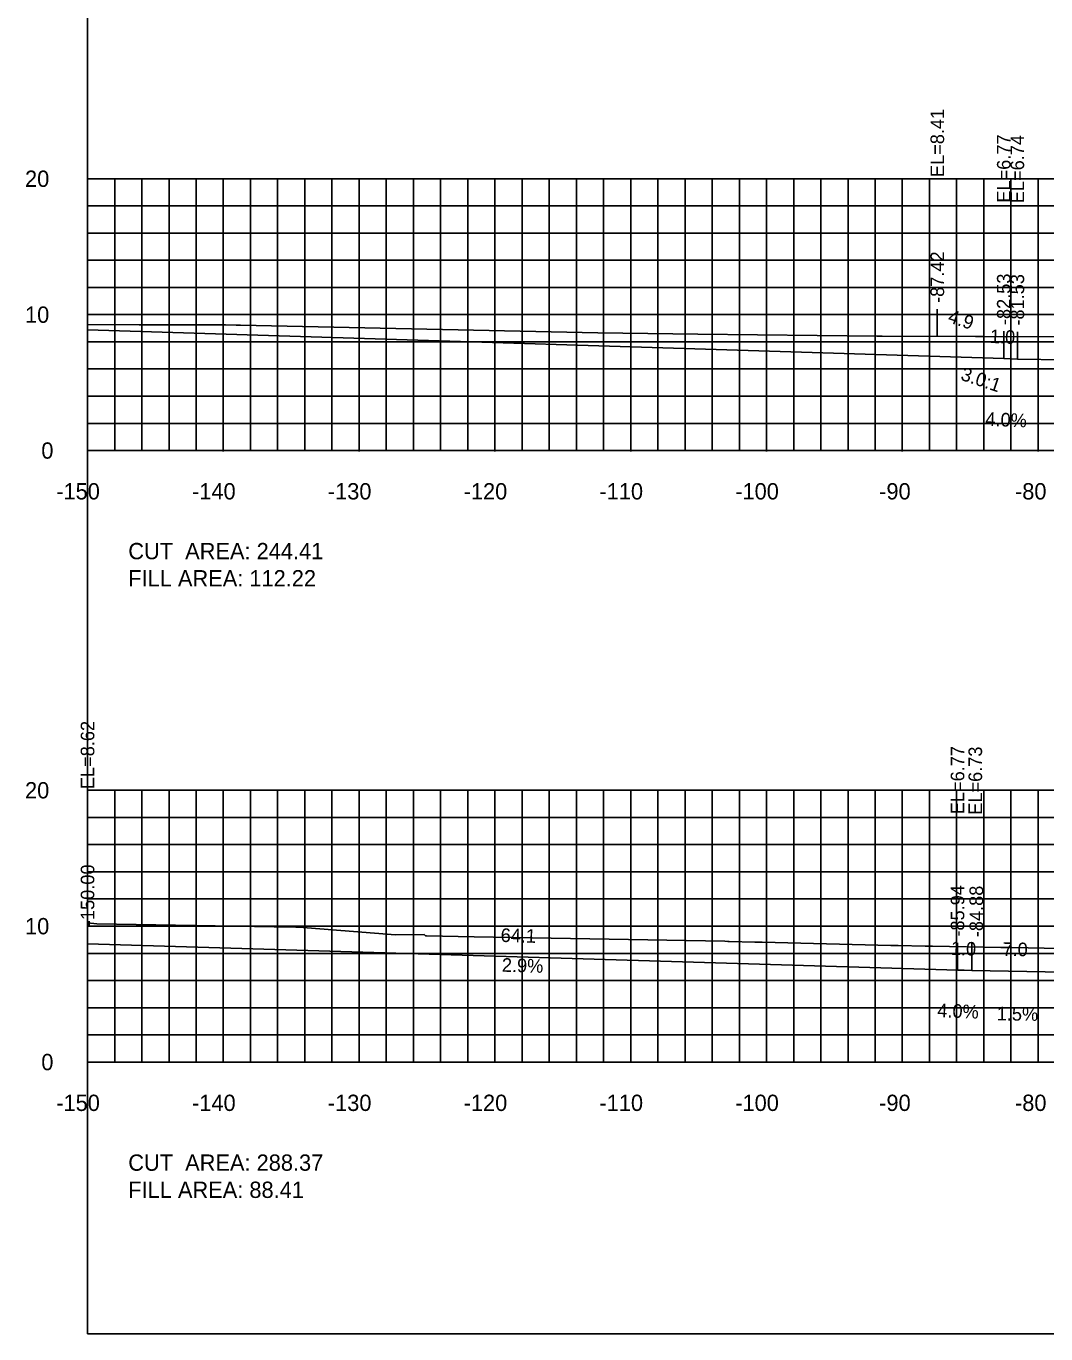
# Model space of a CAD drawing. Extents: x 1797419 to 1809236, y 248759 to 251512.
# Drawn here: x 1806216.5 to 1806291.6, y 250079.4 to 250175.7 of the extents above; entities that cross this region are included whole.
import ezdxf

# ---------------------------------------------------------------- set-up
doc = ezdxf.new("R2010")
doc.units = 0
for name, color, linetype in [('10', 7, 'Continuous'), ('3', 7, 'Continuous'), ('31', 7, 'Continuous'), ('4', 7, 'Continuous'), ('60', 7, 'Continuous'), ('ANNO-TXT', 7, 'Continuous'), ('CL-CNST', 7, 'Continuous'), ('Level 62', 7, 'Continuous'), ('M-ROADS', 7, 'Continuous')]:
    doc.layers.add(name, color=color, linetype=linetype)

msp = doc.modelspace()

# ---------------------------------------------------------------- linework, layer by layer
for p, q in [((1806283.579, 250152.837), (1806283.579, 250154.837)), ((1806288.472, 250151.207), (1806288.472, 250153.207)), ((1806289.472, 250151.167), (1806289.472, 250153.167)), ((1806221.002, 250108.05), (1806221.002, 250110.05)), ((1806285.065, 250106.206), (1806285.065, 250108.206)), ((1806286.118, 250106.164), (1806286.118, 250108.164))]:
    msp.add_line(p, q)
msp.add_lwpolyline([(1806221.002, 250079.432), (1806521.002, 250079.432), (1806521.002, 250269.432), (1806221.002, 250269.432)], close=True)
at = {"layer": '60'}
for p, q in [((1806220.942, 250164.432), (1806221.002, 250164.432)), ((1806221.002, 250144.432), (1806221.002, 250164.432)), ((1806220.942, 250154.432), (1806221.002, 250154.432)), ((1806220.942, 250144.432), (1806221.002, 250144.432)), ((1806221.002, 250144.432), (1806521.002, 250144.432)), ((1806221.002, 250144.372), (1806221.002, 250144.432)), ((1806231.002, 250144.372), (1806231.002, 250144.432)), ((1806241.002, 250144.372), (1806241.002, 250144.432)), ((1806251.002, 250144.372), (1806251.002, 250144.432)), ((1806261.002, 250144.372), (1806261.002, 250144.432)), ((1806271.002, 250144.372), (1806271.002, 250144.432)), ((1806281.002, 250144.372), (1806281.002, 250144.432)), ((1806291.002, 250144.372), (1806291.002, 250144.432)), ((1806220.942, 250119.432), (1806221.002, 250119.432)), ((1806221.002, 250099.432), (1806221.002, 250119.432)), ((1806220.942, 250109.432), (1806221.002, 250109.432)), ((1806220.942, 250099.432), (1806221.002, 250099.432)), ((1806221.002, 250099.432), (1806521.002, 250099.432)), ((1806221.002, 250099.372), (1806221.002, 250099.432)), ((1806231.002, 250099.372), (1806231.002, 250099.432)), ((1806241.002, 250099.372), (1806241.002, 250099.432)), ((1806251.002, 250099.372), (1806251.002, 250099.432)), ((1806261.002, 250099.372), (1806261.002, 250099.432)), ((1806271.002, 250099.372), (1806271.002, 250099.432)), ((1806281.002, 250099.372), (1806281.002, 250099.432)), ((1806291.002, 250099.372), (1806291.002, 250099.432))]:
    msp.add_line(p, q, dxfattribs=at)
at = {"layer": 'CL-CNST'}
for points in [[(1806221.002, 250153.306), (1806288.472, 250151.207), (1806288.958, 250151.188), (1806289.472, 250151.167), (1806292.935, 250151.115), (1806296.472, 250151.062), (1806297.35, 250151.027), (1806298.472, 250150.982), (1806298.801, 250150.982), (1806298.808, 250150.962), (1806298.969, 250150.482), (1806300.378, 250150.595), (1806300.969, 250150.642), (1806349.002, 250151.698), (1806351.001, 250151.742), (1806351.041, 250151.859), (1806351.172, 250152.242), (1806351.502, 250152.242), (1806371.001, 250153.022), (1806378.502, 250152.406)], [(1806221.002, 250108.134), (1806285.085, 250106.205), (1806285.118, 250106.204), (1806285.564, 250106.186), (1806286.118, 250106.164), (1806291.509, 250106.083), (1806293.118, 250106.059)]]:
    msp.add_lwpolyline(points, dxfattribs=at)
at = {"layer": 'Level 62'}
for p, q in [((1806221.002, 250164.432), (1806521.002, 250164.432)), ((1806221.002, 250144.432), (1806221.002, 250164.432)), ((1806223.002, 250144.432), (1806223.002, 250164.432)), ((1806225.002, 250144.432), (1806225.002, 250164.432)), ((1806227.002, 250144.432), (1806227.002, 250164.432)), ((1806229.002, 250144.432), (1806229.002, 250164.432)), ((1806231.002, 250144.432), (1806231.002, 250164.432)), ((1806233.002, 250144.432), (1806233.002, 250164.432)), ((1806235.002, 250144.432), (1806235.002, 250164.432)), ((1806237.002, 250144.432), (1806237.002, 250164.432)), ((1806239.002, 250144.432), (1806239.002, 250164.432)), ((1806241.002, 250144.432), (1806241.002, 250164.432)), ((1806243.002, 250144.432), (1806243.002, 250164.432)), ((1806245.002, 250144.432), (1806245.002, 250164.432)), ((1806247.002, 250144.432), (1806247.002, 250164.432)), ((1806249.002, 250144.432), (1806249.002, 250164.432)), ((1806251.002, 250144.432), (1806251.002, 250164.432)), ((1806253.002, 250144.432), (1806253.002, 250164.432)), ((1806255.002, 250144.432), (1806255.002, 250164.432)), ((1806257.002, 250144.432), (1806257.002, 250164.432)), ((1806259.002, 250144.432), (1806259.002, 250164.432)), ((1806261.002, 250144.432), (1806261.002, 250164.432)), ((1806263.002, 250144.432), (1806263.002, 250164.432)), ((1806265.002, 250144.432), (1806265.002, 250164.432)), ((1806267.002, 250144.432), (1806267.002, 250164.432)), ((1806269.002, 250144.432), (1806269.002, 250164.432)), ((1806271.002, 250144.432), (1806271.002, 250164.432)), ((1806273.002, 250144.432), (1806273.002, 250164.432)), ((1806275.002, 250144.432), (1806275.002, 250164.432)), ((1806277.002, 250144.432), (1806277.002, 250164.432)), ((1806279.002, 250144.432), (1806279.002, 250164.432)), ((1806281.002, 250144.432), (1806281.002, 250164.432)), ((1806283.002, 250144.432), (1806283.002, 250164.432)), ((1806285.002, 250144.432), (1806285.002, 250164.432)), ((1806287.002, 250144.432), (1806287.002, 250164.432)), ((1806289.002, 250144.432), (1806289.002, 250164.432)), ((1806291.002, 250144.432), (1806291.002, 250164.432)), ((1806221.002, 250162.432), (1806521.002, 250162.432)), ((1806221.002, 250160.432), (1806521.002, 250160.432)), ((1806221.002, 250158.432), (1806521.002, 250158.432)), ((1806221.002, 250156.432), (1806521.002, 250156.432)), ((1806221.002, 250154.432), (1806521.002, 250154.432)), ((1806221.002, 250152.432), (1806521.002, 250152.432)), ((1806221.002, 250150.432), (1806521.002, 250150.432)), ((1806221.002, 250148.432), (1806521.002, 250148.432)), ((1806221.002, 250146.432), (1806521.002, 250146.432)), ((1806221.002, 250144.432), (1806521.002, 250144.432)), ((1806221.002, 250119.432), (1806521.002, 250119.432)), ((1806221.002, 250099.432), (1806221.002, 250119.432)), ((1806223.002, 250099.432), (1806223.002, 250119.432)), ((1806225.002, 250099.432), (1806225.002, 250119.432)), ((1806227.002, 250099.432), (1806227.002, 250119.432)), ((1806229.002, 250099.432), (1806229.002, 250119.432)), ((1806231.002, 250099.432), (1806231.002, 250119.432)), ((1806233.002, 250099.432), (1806233.002, 250119.432)), ((1806235.002, 250099.432), (1806235.002, 250119.432)), ((1806237.002, 250099.432), (1806237.002, 250119.432)), ((1806239.002, 250099.432), (1806239.002, 250119.432)), ((1806241.002, 250099.432), (1806241.002, 250119.432)), ((1806243.002, 250099.432), (1806243.002, 250119.432)), ((1806245.002, 250099.432), (1806245.002, 250119.432)), ((1806247.002, 250099.432), (1806247.002, 250119.432)), ((1806249.002, 250099.432), (1806249.002, 250119.432)), ((1806251.002, 250099.432), (1806251.002, 250119.432)), ((1806253.002, 250099.432), (1806253.002, 250119.432)), ((1806255.002, 250099.432), (1806255.002, 250119.432)), ((1806257.002, 250099.432), (1806257.002, 250119.432)), ((1806259.002, 250099.432), (1806259.002, 250119.432)), ((1806261.002, 250099.432), (1806261.002, 250119.432)), ((1806263.002, 250099.432), (1806263.002, 250119.432)), ((1806265.002, 250099.432), (1806265.002, 250119.432)), ((1806267.002, 250099.432), (1806267.002, 250119.432)), ((1806269.002, 250099.432), (1806269.002, 250119.432)), ((1806271.002, 250099.432), (1806271.002, 250119.432)), ((1806273.002, 250099.432), (1806273.002, 250119.432)), ((1806275.002, 250099.432), (1806275.002, 250119.432)), ((1806277.002, 250099.432), (1806277.002, 250119.432)), ((1806279.002, 250099.432), (1806279.002, 250119.432)), ((1806281.002, 250099.432), (1806281.002, 250119.432)), ((1806283.002, 250099.432), (1806283.002, 250119.432)), ((1806285.002, 250099.432), (1806285.002, 250119.432)), ((1806287.002, 250099.432), (1806287.002, 250119.432)), ((1806289.002, 250099.432), (1806289.002, 250119.432)), ((1806291.002, 250099.432), (1806291.002, 250119.432)), ((1806221.002, 250117.432), (1806521.002, 250117.432)), ((1806221.002, 250115.432), (1806521.002, 250115.432)), ((1806221.002, 250113.432), (1806521.002, 250113.432)), ((1806221.002, 250111.432), (1806521.002, 250111.432)), ((1806221.002, 250109.432), (1806521.002, 250109.432)), ((1806221.002, 250107.432), (1806521.002, 250107.432)), ((1806221.002, 250105.432), (1806521.002, 250105.432)), ((1806221.002, 250103.432), (1806521.002, 250103.432)), ((1806221.002, 250101.432), (1806521.002, 250101.432)), ((1806221.002, 250099.432), (1806521.002, 250099.432))]:
    msp.add_line(p, q, dxfattribs=at)
at = {"layer": 'M-ROADS'}
for points in [[(1806221.002, 250153.705), (1806224.794, 250153.692), (1806230.688, 250153.671), (1806231.168, 250153.673), (1806231.936, 250153.659), (1806231.976, 250153.66), (1806232.276, 250153.648), (1806258.57, 250153.093), (1806265.934, 250152.985), (1806279.121, 250152.852), (1806279.308, 250152.853), (1806279.527, 250152.851), (1806286.384, 250152.828), (1806286.571, 250152.828), (1806286.919, 250152.828), (1806298.866, 250152.773)], [(1806221.002, 250109.673), (1806221.689, 250109.615), (1806234.756, 250109.39), (1806236.338, 250109.348), (1806236.561, 250109.356), (1806243.677, 250108.805), (1806245.787, 250108.827), (1806245.894, 250108.727), (1806245.9, 250108.726), (1806245.926, 250108.72), (1806245.95, 250108.714), (1806245.962, 250108.711), (1806249.464, 250108.648), (1806267.943, 250108.32), (1806268.141, 250108.315), (1806268.246, 250108.305), (1806270.139, 250108.245), (1806270.294, 250108.245), (1806270.676, 250108.244), (1806280.166, 250108.014), (1806280.63, 250108.005), (1806280.708, 250108.003), (1806282.694, 250107.966), (1806283.235, 250107.966), (1806288.261, 250107.87), (1806289.077, 250107.854), (1806295.03, 250107.749)]]:
    msp.add_lwpolyline(points, dxfattribs=at)

# ---------------------------------------------------------------- texts
msp.add_text('3.0:1', height=1, rotation=341.57445).set_placement((1806285.235, 250149.65))
at = {"layer": '10'}
for s, p in [('-150', (1806218.698, 250140.832)), ('-140', (1806228.698, 250140.832)), ('-130', (1806238.698, 250140.832)), ('-120', (1806248.698, 250140.832)), ('-110', (1806258.698, 250140.832)), ('-100', (1806268.698, 250140.832)), ('-90', (1806279.298, 250140.832)), ('-80', (1806289.298, 250140.832)), ('-150', (1806218.698, 250095.832)), ('-140', (1806228.698, 250095.832)), ('-130', (1806238.698, 250095.832)), ('-120', (1806248.698, 250095.832)), ('-110', (1806258.698, 250095.832)), ('-100', (1806268.698, 250095.832)), ('-90', (1806279.298, 250095.832)), ('-80', (1806289.298, 250095.832))]:
    msp.add_text(s, height=1.2, dxfattribs=at).set_placement(p)
at = {"layer": '3'}
for s, p in [('EL=8.41', (1806284.079, 250164.554)), ('EL=6.77', (1806288.972, 250162.672)), ('EL=6.74', (1806289.972, 250162.632)), ('-87.42', (1806284.079, 250155.294)), ('-82.53', (1806288.972, 250153.664)), ('-81.53', (1806289.972, 250153.624)), ('EL=8.62', (1806221.502, 250119.515)), ('EL=6.77', (1806285.565, 250117.67)), ('EL=6.73', (1806286.875, 250117.629)), ('-150.00', (1806221.502, 250109.436)), ('-85.94', (1806285.565, 250108.662)), ('-84.88', (1806286.952, 250108.621))]:
    msp.add_text(s, height=1, rotation=90, dxfattribs=at).set_placement(p)
at = {"layer": '31'}
for s, p in [('20', (1806216.4, 250163.832)), ('10', (1806216.4, 250153.832)), ('0', (1806217.6, 250143.832)), ('20', (1806216.4, 250118.832)), ('10', (1806216.4, 250108.832)), ('0', (1806217.6, 250098.832))]:
    msp.add_text(s, height=1.2, dxfattribs=at).set_placement(p)
at = {"layer": '4'}
for s, rotation, p in [('4.9', 341.57445, (1806284.294, 250153.896)), ('1.0', 357.71073, (1806287.437, 250152.349)), ('4.0%', 357.71073, (1806287.104, 250146.258)), ('64.1', 358.35042, (1806251.412, 250108.275)), ('1.0', 357.70957, (1806284.563, 250107.327)), ('7.0', 359.14057, (1806288.371, 250107.243)), ('2.9%', 358.35042, (1806251.502, 250106.082)), ('4.0%', 357.70957, (1806283.563, 250102.745)), ('1.5%', 359.14057, (1806287.95, 250102.503))]:
    msp.add_text(s, height=1, rotation=rotation, dxfattribs=at).set_placement(p)
at = {"layer": '60'}
for p in [(1806221.002, 250144.432), (1806221.002, 250099.432)]:
    msp.add_text('-', height=0.0001, dxfattribs=at).set_placement(p)
at = {"layer": 'ANNO-TXT'}
for s, p in [('CUT  AREA: 244.41', (1806224.002, 250136.432)), ('FILL AREA: 112.22', (1806224.002, 250134.432)), ('CUT  AREA: 288.37', (1806224.002, 250091.432)), ('FILL AREA: 88.41', (1806224.002, 250089.432))]:
    msp.add_text(s, height=1.2, dxfattribs=at).set_placement(p)

doc.saveas('drawing.dxf')
